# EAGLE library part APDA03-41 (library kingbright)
Kingbrite dual display smd display with .3" character height Ordered from mouser
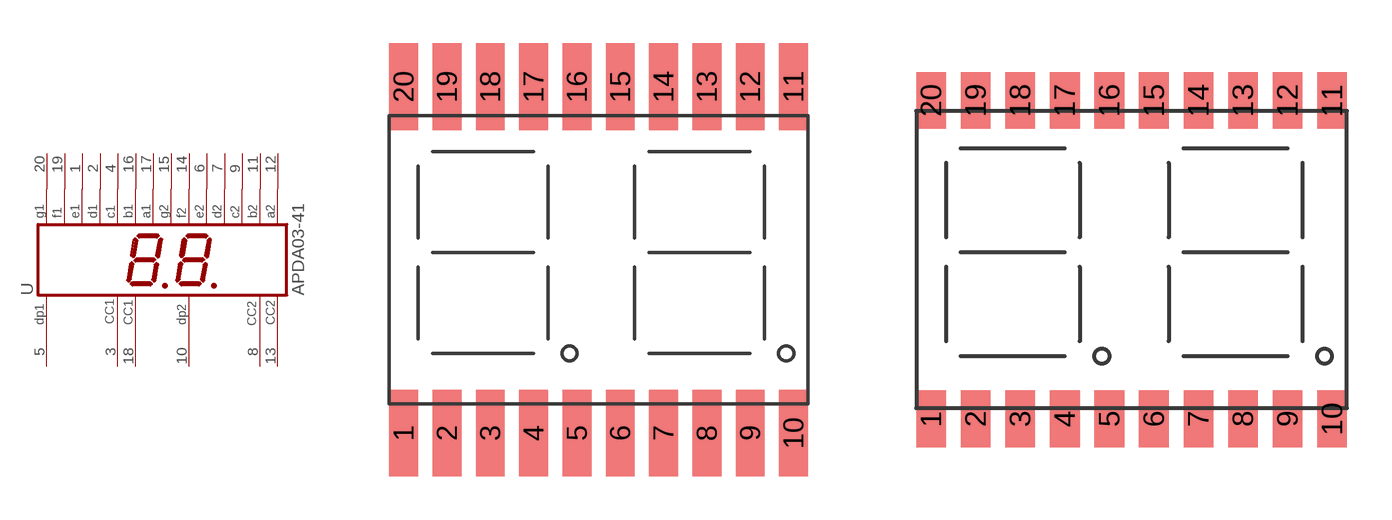
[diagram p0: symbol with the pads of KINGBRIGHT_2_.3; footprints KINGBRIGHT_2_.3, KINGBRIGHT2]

Designator prefix -

## APDA03-41LONG  [KINGBRIGHT_2_.3]
1  E1  pas
2  D1  pas
3  CC1A  pas
4  C1  pas
5  DP1  pas
6  E2  pas
7  D2  pas
8  CC2A  pas
9  C2  pas
10  DP2  pas
11  B2  pas
12  A2  pas
13  CC2B  pas
14  F2  pas
15  G2  pas
16  B1  pas
17  A1  pas
18  CC1B  pas
19  F1  pas
20  G1  pas

## APDA03-41SHORT  [KINGBRIGHT2]
Pads as for KINGBRIGHT_2_.3

## Footprint KINGBRIGHT_2_.3 (pad centres in mm)
SMD LED .3" Character height package SMD pads on kingbright datasheet are 1.3x1.0 in this package they are 1.5x1.0 to make it easier to hand solder. Additionally, the characters drawn on aren't to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
smd 1 x 3: 1 -6.25,-5.5; 2 -4.75,-5.5; 3 -3.25,-5.5; 4 -1.75,-5.5; 5 -0.25,-5.5; 6 1.25,-5.5; 7 2.75,-5.5; 8 4.25,-5.5; 9 5.75,-5.5; 10 7.25,-5.5; 11 7.25,6.5; 12 5.75,6.5; 13 4.25,6.5; 14 2.75,6.5; 15 1.25,6.5; 16 -0.25,6.5; 17 -1.75,6.5; 18 -3.25,6.5; 19 -4.75,6.5; 20 -6.25,6.5

## Footprint KINGBRIGHT2 (pad centres in mm)
see description for kingbright 2_3 This package just has smaller smd pads
smd 1 x 1.905: 1 -6.25,-4.865; 2 -4.75,-4.865; 3 -3.25,-4.865; 4 -1.75,-4.865; 5 -0.25,-4.865; 6 1.25,-4.865; 7 2.75,-4.865; 8 4.25,-4.865; 9 5.75,-4.865; 10 7.25,-4.865; 11 7.25,5.865; 12 5.75,5.865; 13 4.25,5.865; 14 2.75,5.865; 15 1.25,5.865; 16 -0.25,5.865; 17 -1.75,5.865; 18 -3.25,5.865; 19 -4.75,5.865; 20 -6.25,5.865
